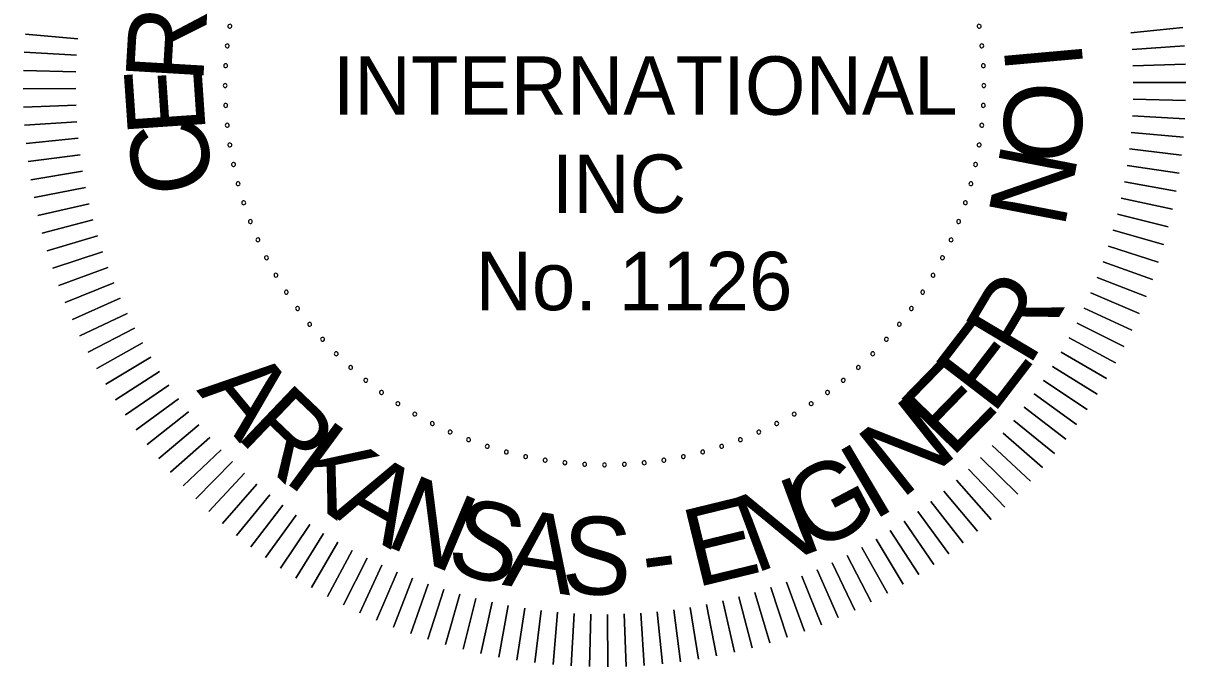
# Model space of a CAD drawing. Extents: x -31696 to 27919, y -8775 to 11152.
# Drawn here: x 10429 to 12918, y -7180 to -5802 of the extents above; entities that cross this region are included whole.
import ezdxf

# ---------------------------------------------------------------- set-up
doc = ezdxf.new("R2010")
doc.units = 0
doc.layers.add('Level 47', color=7, linetype='Continuous')

msp = doc.modelspace()

# ---------------------------------------------------------------- linework, layer by layer
at = {"layer": 'Level 47'}
for points in [[(12911.6, -5811.8), (12799.9, -5823)], [(12799.9, -5823), (12911.6, -5811.8)], [(10545.6, -5835.5), (10433.8, -5825.6)], [(10433.8, -5825.6), (10545.6, -5835.5)], [(10543, -5871), (10431, -5864.6)], [(10431, -5864.6), (10543, -5871)], [(12914.9, -5850.8), (12802.9, -5858.4)], [(12802.9, -5858.4), (12914.9, -5850.8)], [(12916.9, -5889.8), (12804.8, -5893.9)], [(12804.8, -5893.9), (12916.9, -5889.8)], [(10541.6, -5906.6), (10429.4, -5903.7)], [(10429.4, -5903.7), (10541.6, -5906.6)], [(10541.2, -5942.1), (10429, -5942.7)], [(10429, -5942.7), (10541.2, -5942.1)], [(12917.8, -5928.9), (12805.5, -5929.5)], [(12805.5, -5929.5), (12917.8, -5928.9)], [(12917.4, -5968), (12805.2, -5965.1)], [(12805.2, -5965.1), (12917.4, -5968)], [(10542, -5977.7), (10429.8, -5981.8)], [(10429.8, -5981.8), (10542, -5977.7)], [(10543.8, -6013.2), (10431.9, -6020.9)], [(10431.9, -6020.9), (10543.8, -6013.2)], [(12915.7, -6007), (12803.7, -6000.6)], [(12803.7, -6000.6), (12915.7, -6007)], [(12912.9, -6046), (12801.1, -6036.1)], [(12801.1, -6036.1), (12912.9, -6046)], [(10546.8, -6048.6), (10435.1, -6059.8)], [(10435.1, -6059.8), (10546.8, -6048.6)], [(12908.8, -6084.9), (12797.4, -6071.4)], [(12797.4, -6071.4), (12908.8, -6084.9)], [(10550.9, -6084), (10439.7, -6098.7)], [(10439.7, -6098.7), (10550.9, -6084)], [(10556.1, -6119.2), (10445.4, -6137.3)], [(10445.4, -6137.3), (10556.1, -6119.2)], [(12903.5, -6123.6), (12792.6, -6106.7)], [(12792.6, -6106.7), (12903.5, -6123.6)], [(12897, -6162.2), (12786.7, -6141.8)], [(12786.7, -6141.8), (12897, -6162.2)], [(10562.4, -6154.2), (10452.3, -6175.8)], [(10452.3, -6175.8), (10562.4, -6154.2)], [(10569.8, -6188.9), (10460.5, -6214)], [(10460.5, -6214), (10569.8, -6188.9)], [(12889.3, -6200.5), (12779.6, -6176.6)], [(12779.6, -6176.6), (12889.3, -6200.5)], [(12880.4, -6238.6), (12771.5, -6211.3)], [(12771.5, -6211.3), (12880.4, -6238.6)], [(10578.3, -6223.5), (10469.8, -6252)], [(10469.8, -6252), (10578.3, -6223.5)], [(12870.3, -6276.3), (12762.3, -6245.6)], [(12762.3, -6245.6), (12870.3, -6276.3)], [(10587.9, -6257.7), (10480.3, -6289.6)], [(10480.3, -6289.6), (10587.9, -6257.7)], [(10598.6, -6291.7), (10492, -6326.9)], [(10492, -6326.9), (10598.6, -6291.7)], [(12859, -6313.8), (12752.1, -6279.7)], [(12752.1, -6279.7), (12859, -6313.8)], [(12846.5, -6350.8), (12740.7, -6313.4)], [(12740.7, -6313.4), (12846.5, -6350.8)], [(10610.3, -6325.3), (10504.9, -6363.9)], [(10504.9, -6363.9), (10610.3, -6325.3)], [(10623, -6358.5), (10518.9, -6400.3)], [(10518.9, -6400.3), (10623, -6358.5)], [(12832.9, -6387.5), (12728.4, -6346.7)], [(12728.4, -6346.7), (12832.9, -6387.5)], [(10636.8, -6391.2), (10534.1, -6436.4)], [(10534.1, -6436.4), (10636.8, -6391.2)], [(12818.2, -6423.7), (12714.9, -6379.7)], [(12714.9, -6379.7), (12818.2, -6423.7)], [(12802.3, -6459.4), (12700.5, -6412.2)], [(12700.5, -6412.2), (12802.3, -6459.4)], [(10651.6, -6423.6), (10550.4, -6471.9)], [(10550.4, -6471.9), (10651.6, -6423.6)], [(12785.3, -6494.6), (12685, -6444.2)], [(12685, -6444.2), (12785.3, -6494.6)], [(10667.5, -6455.4), (10567.8, -6506.9)], [(10567.8, -6506.9), (10667.5, -6455.4)], [(10684.3, -6486.8), (10586.2, -6541.4)], [(10586.2, -6541.4), (10684.3, -6486.8)], [(12767.2, -6529.2), (12668.5, -6475.7)], [(12668.5, -6475.7), (12767.2, -6529.2)], [(10702.1, -6517.6), (10605.8, -6575.2)], [(10605.8, -6575.2), (10702.1, -6517.6)], [(12748, -6563.3), (12651.1, -6506.7)], [(12651.1, -6506.7), (12748, -6563.3)], [(12727.8, -6596.7), (12632.7, -6537.1)], [(12632.7, -6537.1), (12727.8, -6596.7)], [(10720.8, -6547.8), (10626.4, -6608.4)], [(10626.4, -6608.4), (10720.8, -6547.8)], [(12706.5, -6629.5), (12613.3, -6567)], [(12613.3, -6567), (12706.5, -6629.5)], [(10740.5, -6577.4), (10648.1, -6641)], [(10648.1, -6641), (10740.5, -6577.4)], [(10761.1, -6606.4), (10670.7, -6672.9)], [(10670.7, -6672.9), (10761.1, -6606.4)], [(12684.2, -6661.6), (12593, -6596.2)], [(12593, -6596.2), (12684.2, -6661.6)], [(10782.6, -6634.7), (10694.4, -6704)], [(10694.4, -6704), (10782.6, -6634.7)], [(12660.9, -6693), (12571.8, -6624.7)], [(12571.8, -6624.7), (12660.9, -6693)], [(10805, -6662.3), (10719, -6734.4)], [(10719, -6734.4), (10805, -6662.3)], [(12636.6, -6723.7), (12549.7, -6652.6)], [(12549.7, -6652.6), (12636.6, -6723.7)], [(10828.3, -6689.3), (10744.5, -6763.9)], [(10744.5, -6763.9), (10828.3, -6689.3)], [(12611.4, -6753.5), (12526.8, -6679.8)], [(12526.8, -6679.8), (12611.4, -6753.5)], [(10852.4, -6715.4), (10771, -6792.7)], [(10771, -6792.7), (10852.4, -6715.4)], [(12585.2, -6782.6), (12503, -6706.2)], [(12503, -6706.2), (12585.2, -6782.6)], [(10877.3, -6740.8), (10798.4, -6820.6)], [(10798.4, -6820.6), (10877.3, -6740.8)], [(12558.2, -6810.8), (12478.4, -6731.9)], [(12478.4, -6731.9), (12558.2, -6810.8)], [(10902.9, -6765.4), (10826.6, -6847.7)], [(10826.6, -6847.7), (10902.9, -6765.4)], [(12530.3, -6838.2), (12453, -6756.8)], [(12453, -6756.8), (12530.3, -6838.2)], [(10855.6, -6873.8), (10929.4, -6789.2)], [(10929.4, -6789.2), (10855.6, -6873.8)], [(12501.5, -6864.7), (12426.8, -6780.9)], [(12426.8, -6780.9), (12501.5, -6864.7)], [(10885.5, -6899.1), (10956.6, -6812.2)], [(10956.6, -6812.2), (10885.5, -6899.1)], [(12471.9, -6890.2), (12399.9, -6804.1)], [(12399.9, -6804.1), (12471.9, -6890.2)], [(10916.2, -6923.3), (10984.4, -6834.3)], [(10984.4, -6834.3), (10916.2, -6923.3)], [(12441.5, -6914.8), (12372.3, -6826.5)], [(12372.3, -6826.5), (12441.5, -6914.8)], [(10947.5, -6946.6), (11013, -6855.5)], [(11013, -6855.5), (10947.5, -6946.6)], [(12378.6, -6961.1), (12315, -6868.7)], [(12315, -6868.7), (12378.6, -6961.1)], [(12410.4, -6938.5), (12343.9, -6848)], [(12343.9, -6848), (12410.4, -6938.5)], [(10979.7, -6968.9), (11042.2, -6875.8)], [(11042.2, -6875.8), (10979.7, -6968.9)], [(12346, -6982.8), (12285.3, -6888.4)], [(12285.3, -6888.4), (12346, -6982.8)], [(11012.4, -6990.2), (11072, -6895.1)], [(11072, -6895.1), (11012.4, -6990.2)], [(11045.9, -7010.4), (11102.5, -6913.5)], [(11102.5, -6913.5), (11045.9, -7010.4)], [(12312.8, -7003.4), (12255.1, -6907.1)], [(12255.1, -6907.1), (12312.8, -7003.4)], [(11080, -7029.6), (11133.5, -6931)], [(11133.5, -6931), (11080, -7029.6)], [(12244.5, -7041.4), (12193, -6941.7)], [(12193, -6941.7), (12244.5, -7041.4)], [(12278.9, -7022.9), (12224.3, -6924.9)], [(12224.3, -6924.9), (12278.9, -7022.9)], [(11114.6, -7047.7), (11165, -6947.4)], [(11165, -6947.4), (11114.6, -7047.7)], [(11149.8, -7064.7), (11197, -6962.9)], [(11197, -6962.9), (11149.8, -7064.7)], [(12209.5, -7058.8), (12161.1, -6957.5)], [(12161.1, -6957.5), (12209.5, -7058.8)], [(11185.5, -7080.6), (11229.5, -6977.4)], [(11229.5, -6977.4), (11185.5, -7080.6)], [(11221.7, -7095.4), (11262.5, -6990.8)], [(11262.5, -6990.8), (11221.7, -7095.4)], [(12137.9, -7090.3), (12096, -6986.2)], [(12096, -6986.2), (12137.9, -7090.3)], [(12173.9, -7075.1), (12128.8, -6972.4)], [(12128.8, -6972.4), (12173.9, -7075.1)], [(11258.4, -7109), (11295.8, -7003.2)], [(11295.8, -7003.2), (11258.4, -7109)], [(11295.4, -7121.4), (11329.5, -7014.5)], [(11329.5, -7014.5), (11295.4, -7121.4)], [(12064.5, -7117.2), (12029.2, -7010.6)], [(12029.2, -7010.6), (12064.5, -7117.2)], [(12101.4, -7104.3), (12062.8, -6998.9)], [(12062.8, -6998.9), (12101.4, -7104.3)], [(11332.9, -7132.7), (11363.6, -7024.8)], [(11363.6, -7024.8), (11332.9, -7132.7)], [(11370.6, -7142.8), (11397.9, -7034)], [(11397.9, -7034), (11370.6, -7142.8)], [(11408.7, -7151.7), (11432.6, -7042.1)], [(11432.6, -7042.1), (11408.7, -7151.7)], [(11951.6, -7148.7), (11926.5, -7039.3)], [(11926.5, -7039.3), (11951.6, -7148.7)], [(11989.6, -7139.4), (11961, -7030.8)], [(11961, -7030.8), (11989.6, -7139.4)], [(12027.2, -7128.9), (11995.3, -7021.3)], [(11995.3, -7021.3), (12027.2, -7128.9)], [(11447, -7159.5), (11467.4, -7049.1)], [(11467.4, -7049.1), (11447, -7159.5)], [(11485.6, -7166), (11502.5, -7055)], [(11502.5, -7055), (11485.6, -7166)], [(11524.3, -7171.3), (11537.7, -7059.8)], [(11537.7, -7059.8), (11524.3, -7171.3)], [(11563.2, -7175.3), (11573.1, -7063.5)], [(11573.1, -7063.5), (11563.2, -7175.3)], [(11602.2, -7178.2), (11608.6, -7066.1)], [(11608.6, -7066.1), (11602.2, -7178.2)], [(11641.2, -7179.8), (11644.1, -7067.6)], [(11644.1, -7067.6), (11641.2, -7179.8)], [(11680.3, -7180.2), (11679.7, -7068)], [(11679.7, -7068), (11680.3, -7180.2)], [(11719.4, -7179.4), (11715.2, -7067.2)], [(11715.2, -7067.2), (11719.4, -7179.4)], [(11758.4, -7177.3), (11750.8, -7065.3)], [(11750.8, -7065.3), (11758.4, -7177.3)], [(11797.4, -7174), (11786.2, -7062.4)], [(11786.2, -7062.4), (11797.4, -7174)], [(11836.2, -7169.5), (11821.5, -7058.3)], [(11821.5, -7058.3), (11836.2, -7169.5)], [(11874.9, -7163.8), (11856.7, -7053.1)], [(11856.7, -7053.1), (11874.9, -7163.8)], [(11913.4, -7156.9), (11891.7, -7046.7)], [(11891.7, -7046.7), (11913.4, -7156.9)]]:
    msp.add_lwpolyline(points, dxfattribs=at)
for centre, start, end in [((10871.2, -5808.8), 81, 261), ((10871.2, -5808.8), 261, 81), ((12475.5, -5808.8), 99, 279), ((12475.5, -5808.8), 279, 99), ((10865.7, -5850.9), 84, 264), ((10865.7, -5850.9), 264, 84), ((12481.1, -5850.9), 96, 276), ((12481.1, -5850.9), 276, 96), ((10862.3, -5893.3), 87, 267), ((10862.3, -5893.3), 267, 87), ((12484.4, -5893.3), 93, 273), ((12484.4, -5893.3), 273, 93), ((10861.2, -5935.8), 90, 270), ((10861.2, -5935.8), 270, 90), ((12485.5, -5935.8), 90, 270), ((12485.5, -5935.8), 270, 90), ((10862.3, -5978.3), 93, 273), ((10862.3, -5978.3), 273, 93), ((12484.4, -5978.3), 87, 267), ((12484.4, -5978.3), 267, 87), ((10865.7, -6020.7), 96, 276), ((10865.7, -6020.7), 276, 96), ((12481.1, -6020.7), 84, 264), ((12481.1, -6020.7), 264, 84), ((10871.2, -6062.9), 99, 279), ((10871.2, -6062.9), 279, 99), ((12475.5, -6062.9), 81, 261), ((12475.5, -6062.9), 261, 81), ((10879, -6104.7), 102, 282), ((10879, -6104.7), 282, 102), ((12467.8, -6104.7), 78, 258), ((12467.8, -6104.7), 258, 78), ((10888.9, -6146), 105, 285), ((10888.9, -6146), 285, 105), ((12457.8, -6146), 75, 255), ((12457.8, -6146), 255, 75), ((10901, -6186.8), 108, 288), ((10901, -6186.8), 288, 108), ((12445.8, -6186.8), 72, 252), ((12445.8, -6186.8), 252, 72), ((10915.2, -6226.9), 111, 291), ((10915.2, -6226.9), 291, 111), ((12431.6, -6226.9), 69, 249), ((12431.6, -6226.9), 249, 69), ((10931.4, -6266.1), 114, 294), ((10931.4, -6266.1), 294, 114), ((12415.3, -6266.1), 66, 246), ((12415.3, -6266.1), 246, 66), ((10949.7, -6304.5), 117, 297), ((10949.7, -6304.5), 297, 117), ((12397, -6304.5), 63, 243), ((12397, -6304.5), 243, 63), ((10970, -6341.9), 120, 300), ((10970, -6341.9), 300, 120), ((12376.7, -6341.9), 60, 240), ((12376.7, -6341.9), 240, 60), ((10992.2, -6378.1), 123, 303), ((10992.2, -6378.1), 303, 123), ((12354.5, -6378.1), 57, 237), ((12354.5, -6378.1), 237, 57), ((11016.3, -6413.2), 126, 306), ((11016.3, -6413.2), 306, 126), ((12330.4, -6413.2), 54, 234), ((12330.4, -6413.2), 234, 54), ((11042.2, -6446.9), 129, 309), ((11042.2, -6446.9), 309, 129), ((12304.5, -6446.9), 51, 231), ((12304.5, -6446.9), 231, 51), ((11069.8, -6479.2), 132, 312), ((11069.8, -6479.2), 312, 132), ((12276.9, -6479.2), 48, 228), ((12276.9, -6479.2), 228, 48), ((11099.1, -6510.1), 135, 315), ((11099.1, -6510.1), 315, 135), ((12247.6, -6510.1), 45, 225), ((12247.6, -6510.1), 225, 45), ((11129.9, -6539.4), 138, 318), ((11129.9, -6539.4), 318, 138), ((12216.8, -6539.4), 42, 222), ((12216.8, -6539.4), 222, 42), ((11162.3, -6567), 141, 321), ((11162.3, -6567), 321, 141), ((12184.5, -6567), 39, 219), ((12184.5, -6567), 219, 39), ((11196, -6592.9), 144, 324), ((11196, -6592.9), 324, 144), ((12150.7, -6592.9), 36, 216), ((12150.7, -6592.9), 216, 36), ((11231, -6616.9), 147, 327), ((11231, -6616.9), 327, 147), ((12115.7, -6616.9), 33, 213), ((12115.7, -6616.9), 213, 33), ((11267.3, -6639.1), 150, 330), ((11267.3, -6639.1), 330, 150), ((12079.4, -6639.1), 30, 210), ((12079.4, -6639.1), 210, 30), ((11304.7, -6659.4), 153, 333), ((11304.7, -6659.4), 333, 153), ((12042.1, -6659.4), 27, 207), ((12042.1, -6659.4), 207, 27), ((11343, -6677.7), 156, 336), ((11343, -6677.7), 336, 156), ((11382.3, -6694), 159, 339), ((11382.3, -6694), 339, 159), ((11964.4, -6694), 21, 201), ((11964.4, -6694), 201, 21), ((12003.7, -6677.7), 24, 204), ((12003.7, -6677.7), 204, 24), ((11422.4, -6708.2), 162, 342), ((11422.4, -6708.2), 342, 162), ((11463.2, -6720.3), 165, 345), ((11463.2, -6720.3), 345, 165), ((11883.6, -6720.3), 15, 195), ((11883.6, -6720.3), 195, 15), ((11924.3, -6708.2), 18, 198), ((11924.3, -6708.2), 198, 18), ((11504.5, -6730.2), 168, 348), ((11504.5, -6730.2), 348, 168), ((11546.3, -6738), 351, 171), ((11546.3, -6738), 171, 351), ((11588.5, -6743.5), 354, 174), ((11588.5, -6743.5), 174, 354), ((11630.9, -6746.8), 357, 177), ((11673.4, -6748), 0, 180), ((11715.9, -6746.8), 3, 183), ((11758.3, -6743.5), 6, 186), ((11758.3, -6743.5), 186, 6), ((11800.4, -6738), 9, 189), ((11800.4, -6738), 189, 9), ((11842.2, -6730.2), 12, 192), ((11842.2, -6730.2), 192, 12), ((11630.9, -6746.8), 177, 357), ((11673.4, -6748), 180, 0), ((11715.9, -6746.8), 183, 3)]:
    msp.add_arc(centre, 4.17, start, end, dxfattribs=at)

# ---------------------------------------------------------------- texts
for s, rotation, p in [('R', 86.6268, (10813.9, -5932.1)), ('I', 275.1216, (12527.5, -5851.7)), ('E', 93.9203, (10820, -6036.2)), ('O', 267.0743, (12533.3, -5923.3)), ('C', 101.2137, (10841.4, -6152.2)), ('N', 259.0269, (12524.5, -6054.4)), ('R', 59.2262, (12582, -6540.2)), ('E', 52.4765, (12504.7, -6642.8)), ('A', 309.5859, (10798.7, -6588.5)), ('E', 45.7268, (12415.8, -6735.6)), ('R', 316.3356, (10881.5, -6686.7)), ('N', 38.4196, (12308.1, -6823.6)), ('K', 323.6428, (10983.4, -6781.4)), ('I', 30.5495, (12247.6, -6869.5)), ('A', 330.3925, (11087.6, -6856.6)), ('G', 27.7404, (12115.8, -6939.4)), ('N', 337.1422, (11199.9, -6919.1)), ('N', 20.4332, (11994.4, -6981.5)), ('E', 13.6835, (11868.8, -7010.9)), ('S', 344.4494, (11328.8, -6971.3)), ('A', 351.1991, (11452.9, -7004.6)), ('S', 357.9489, (11580, -7023.1)), ('-', 7.5077, (11761.9, -7023.5))]:
    msp.add_text(s, height=166.7, rotation=rotation, dxfattribs=at).set_placement(p)
for s, height, p in [(' INTERNATIONAL', 125.016, (11045, -5998.3)), ('INC', 125.02, (11560.2, -6208.5)), (' No. 1126', 125.02, (11350.7, -6416.8))]:
    msp.add_text(s, height=height, dxfattribs=at).set_placement(p)

doc.saveas('drawing.dxf')
